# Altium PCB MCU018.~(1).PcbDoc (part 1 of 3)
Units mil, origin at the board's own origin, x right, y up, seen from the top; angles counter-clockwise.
Board outline 4035 x 4400 mil, 2 copper layers (Top Layer, Bottom Layer), stack 62 mil thick; 270 components, 230 nets, 958 pads, 568 vias.
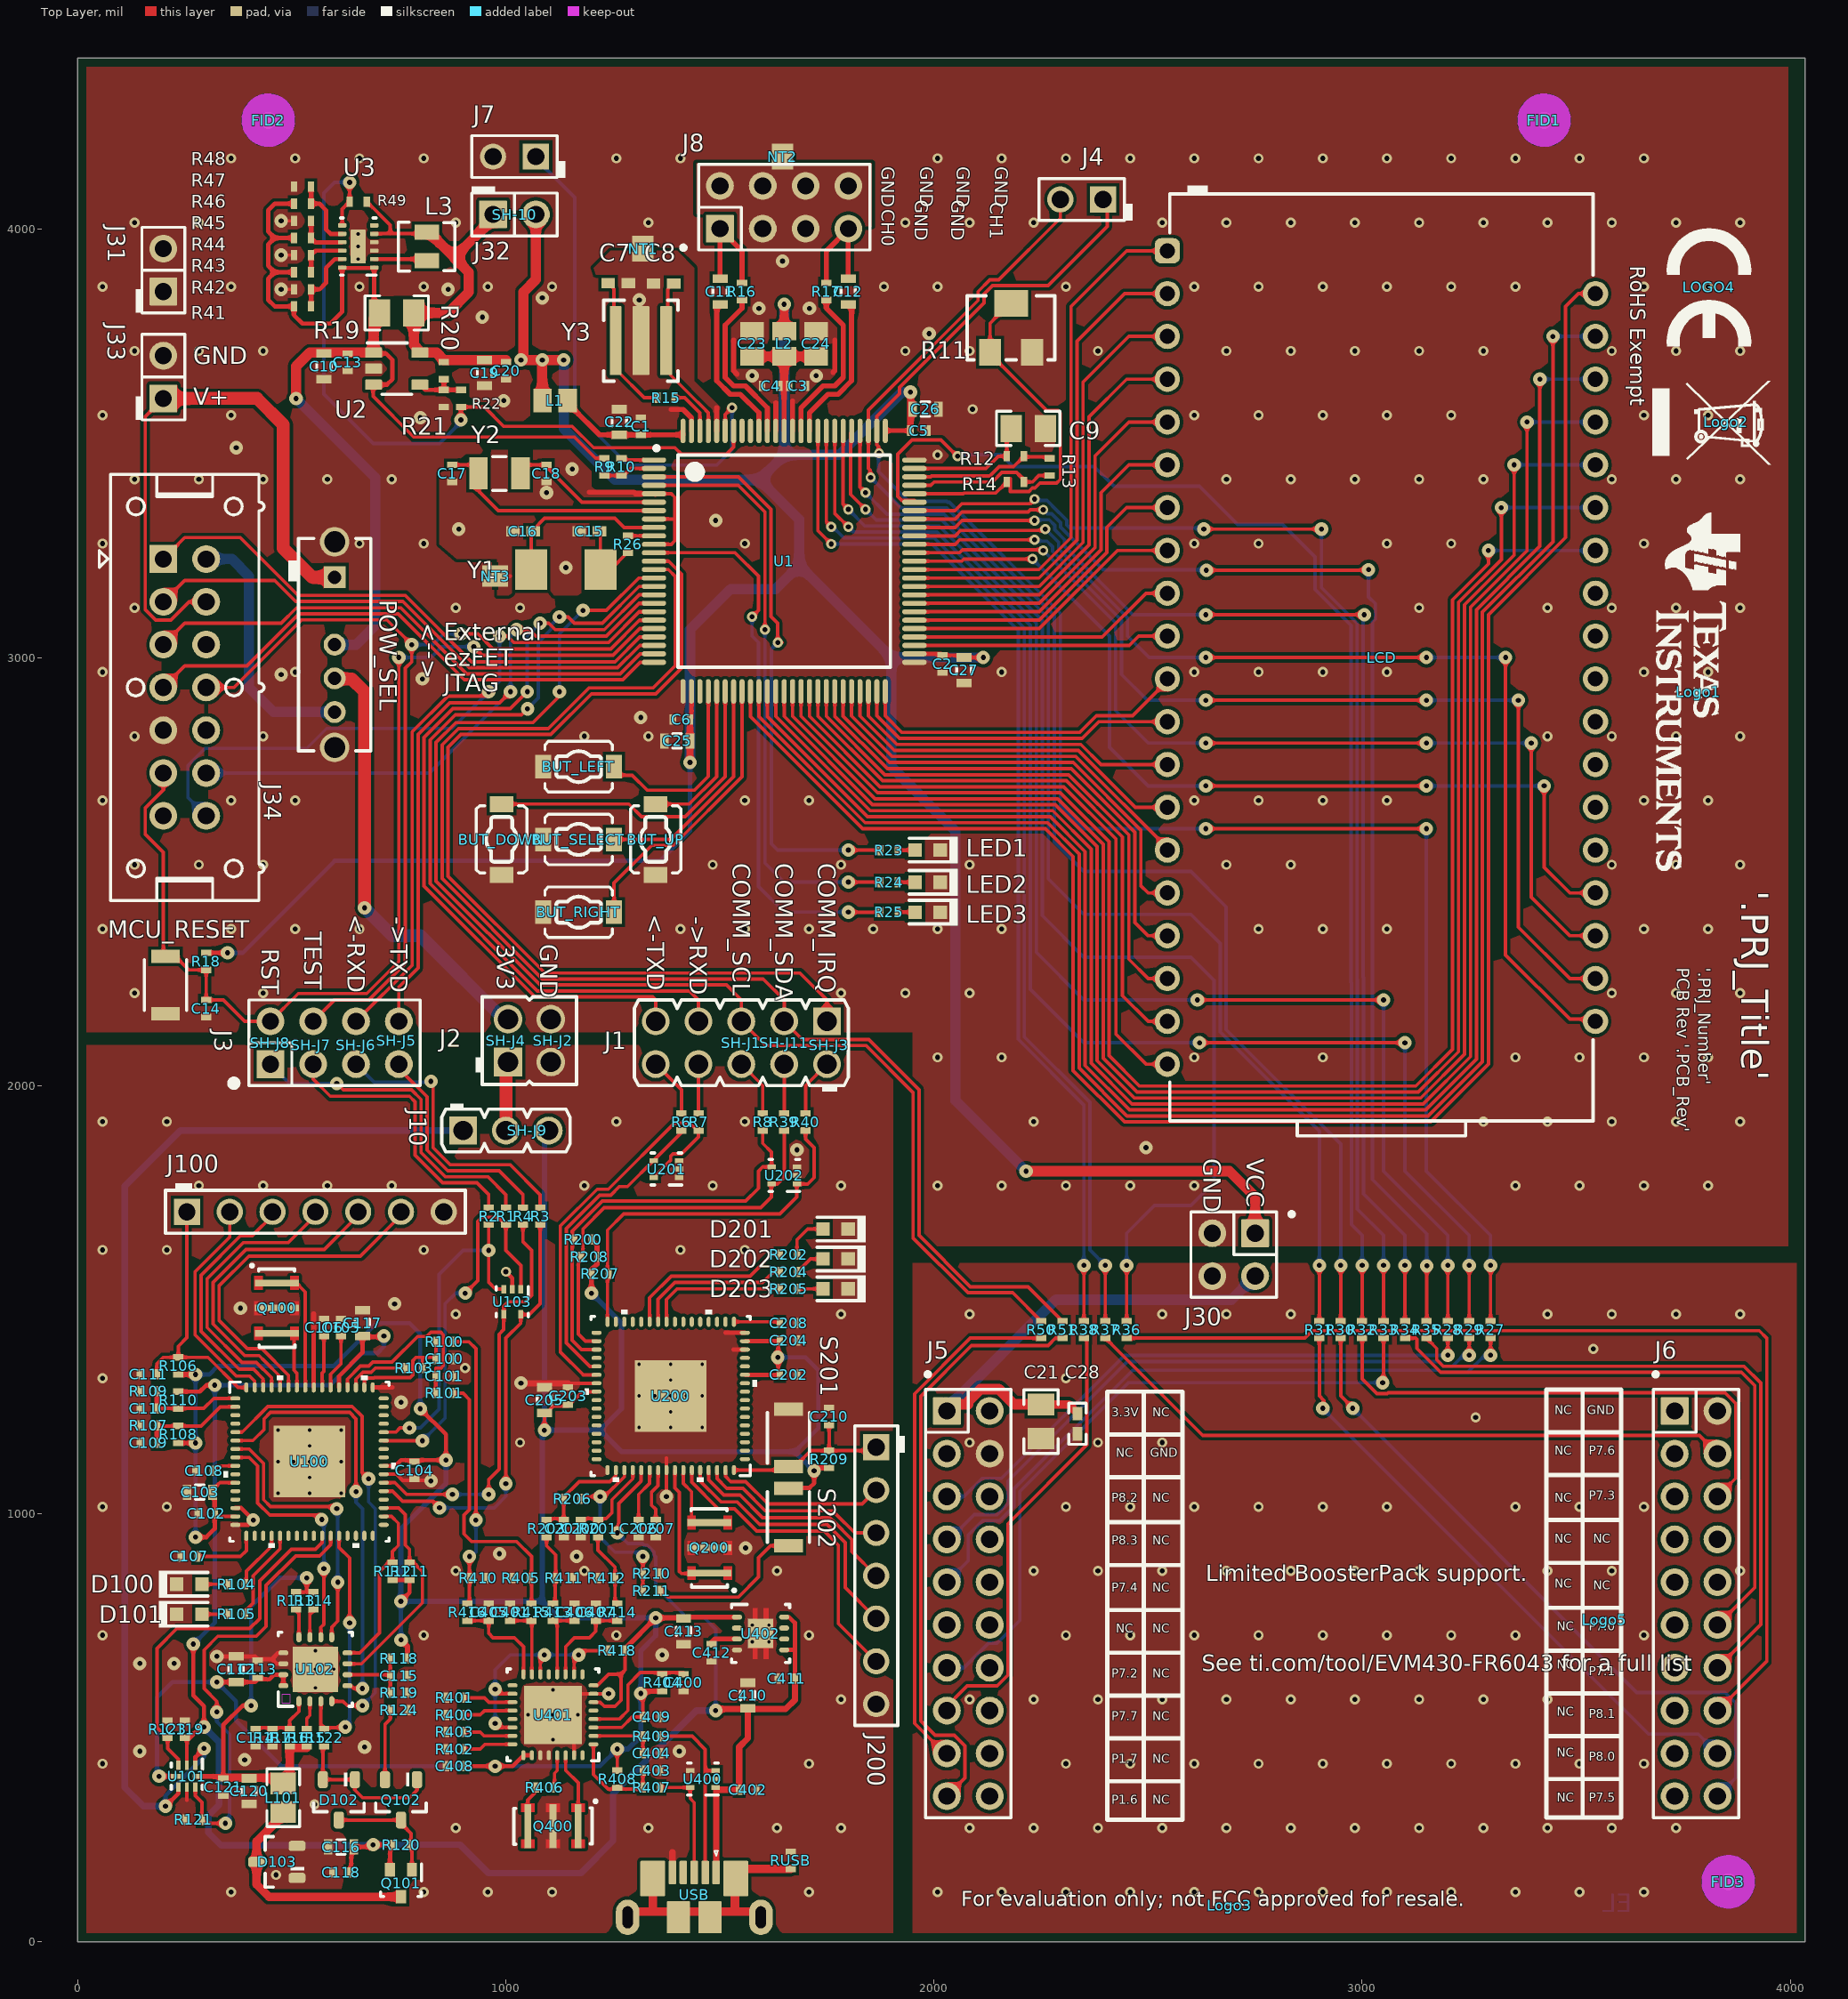
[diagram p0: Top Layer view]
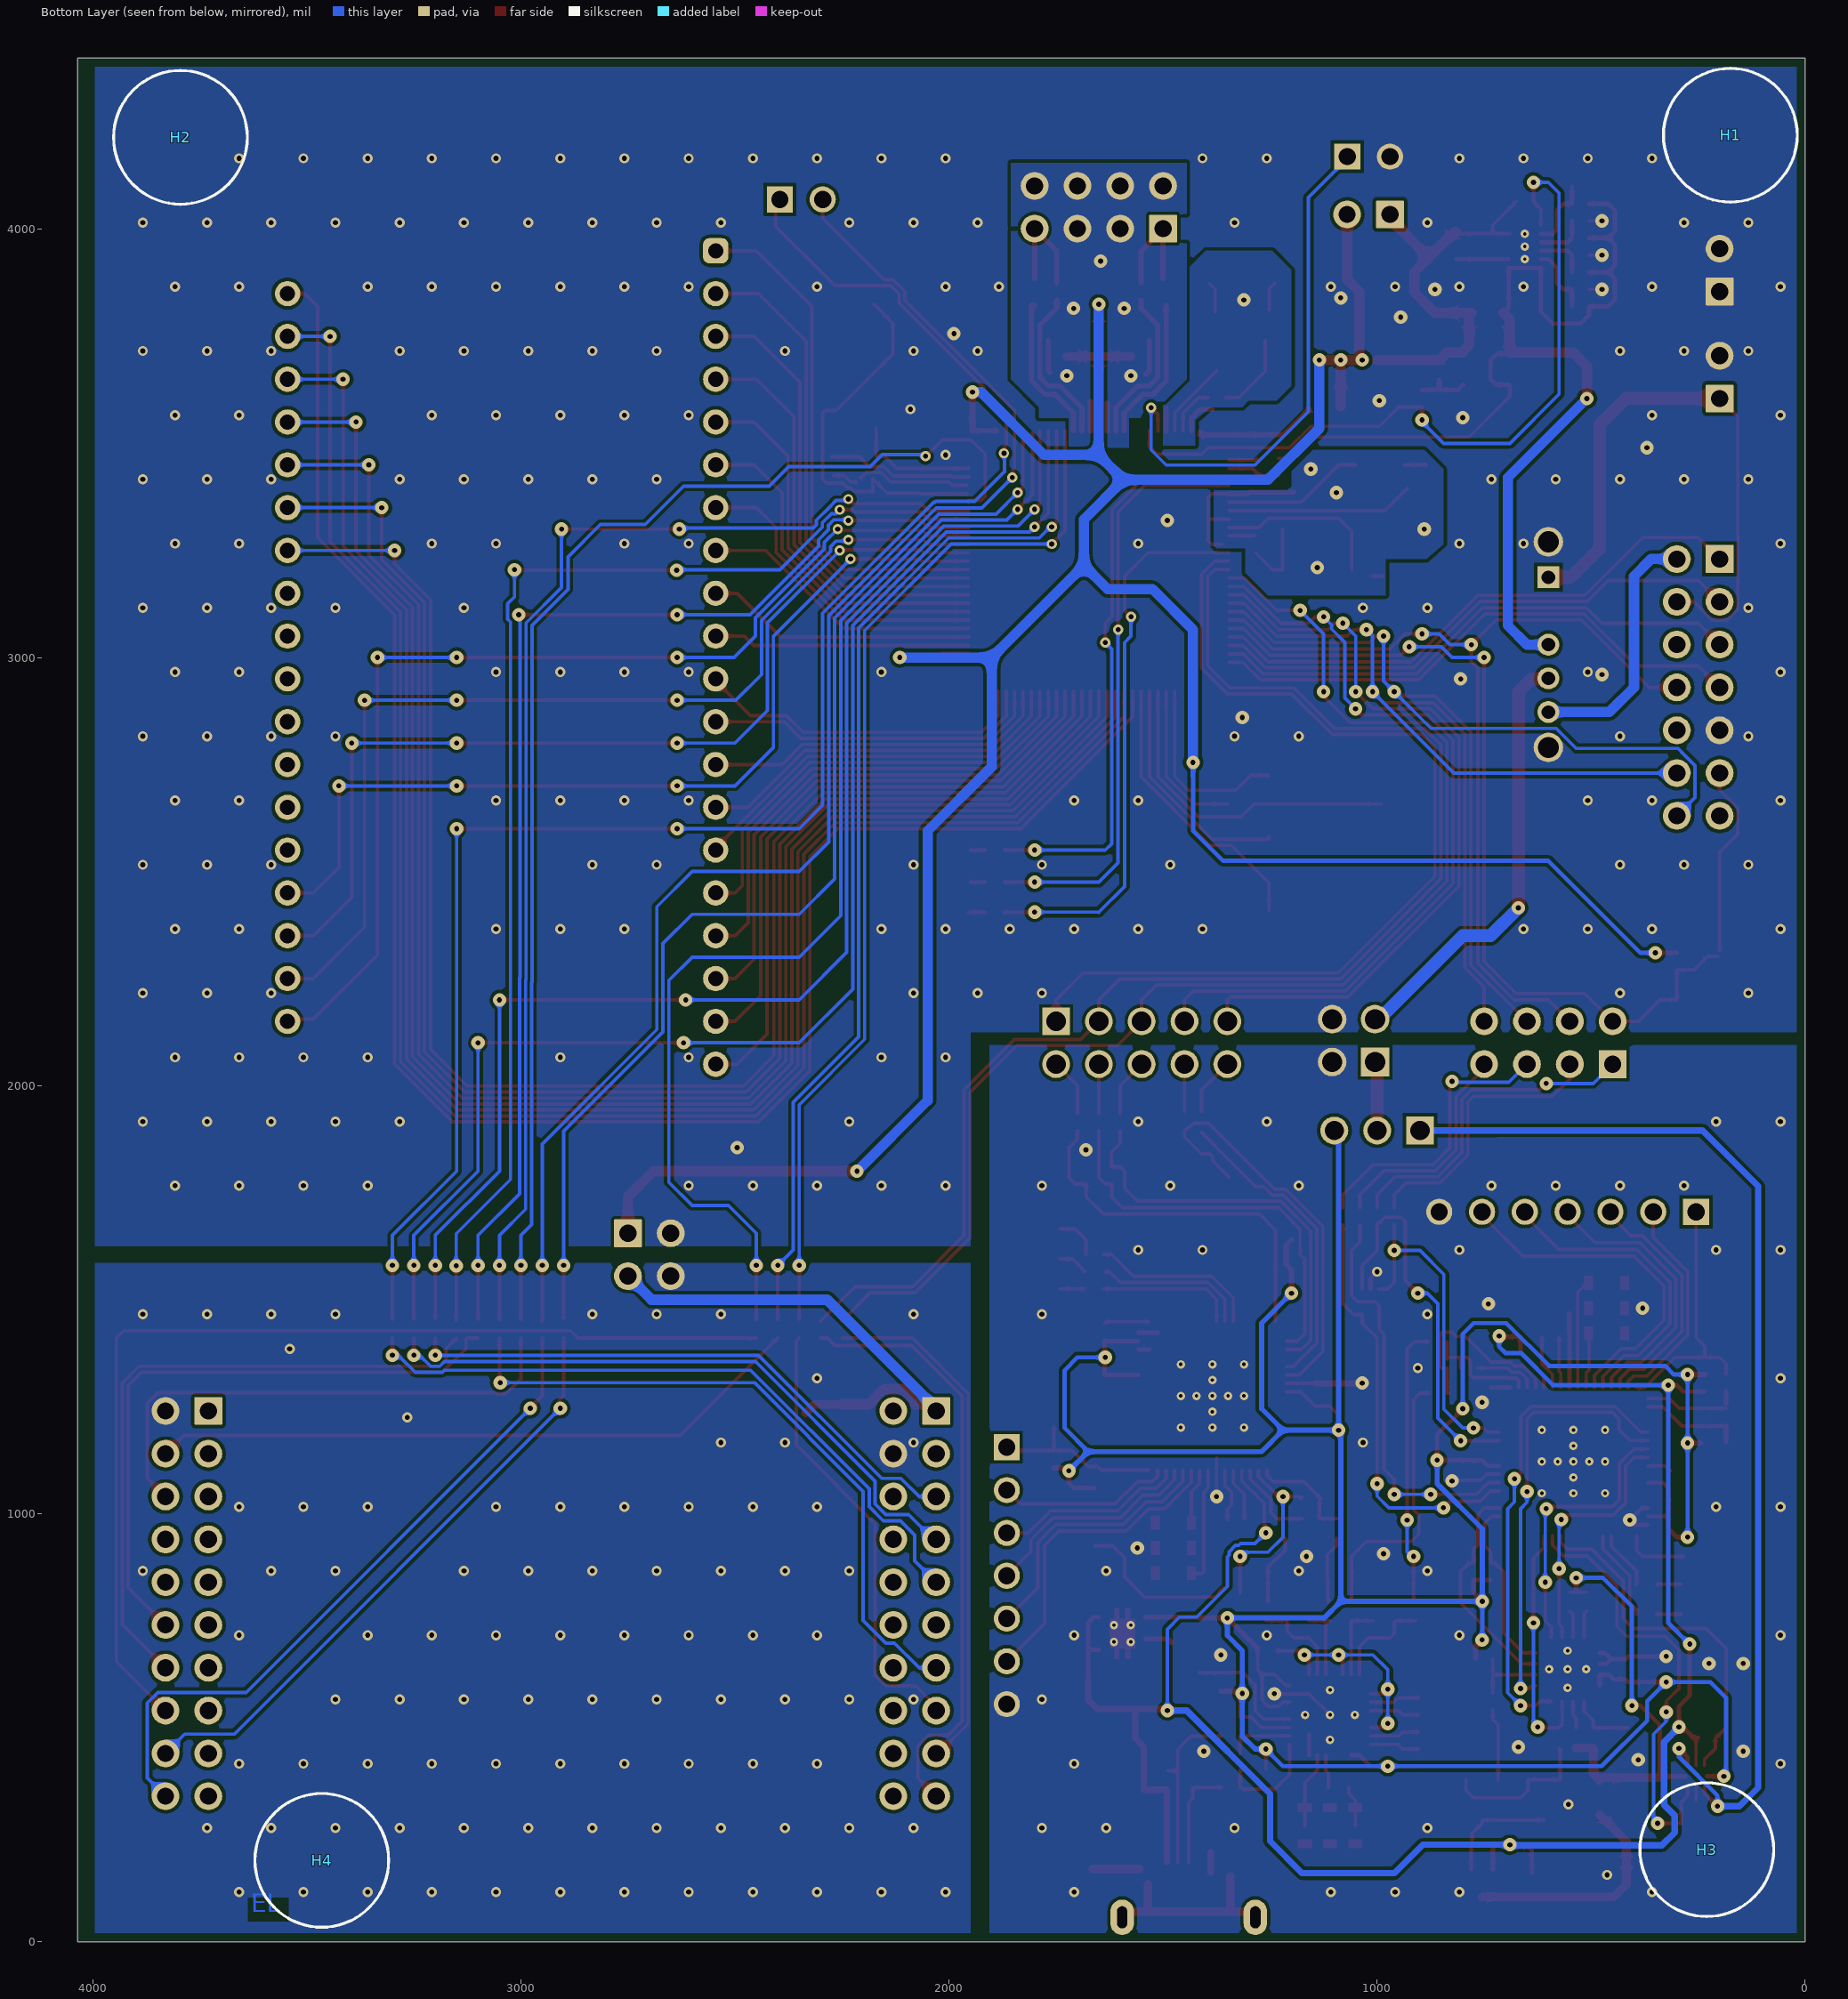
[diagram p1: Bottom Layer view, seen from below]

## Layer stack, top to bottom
Top Solder: solder mask 0.4, Solder Resist, Dk 3.5
Top Layer: signal copper 1.4
Dielectric1: core 59.2, FR-4, Dk 4.8
Bottom Layer: signal copper 1.4
Bottom Solder: solder mask 0.4, Solder Resist, Dk 3.5

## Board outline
0,0 0,4400 4035,4400 4035,0

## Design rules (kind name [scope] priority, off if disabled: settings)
AcuteAngle [All] p1: minimum=4.50000000000000E+0001 checktracksonly=FALSE
AssemblyTestPointUsage [All] p1: valid=2
BoardOutlineClearance BoardOutlineClearance_2 [InComponent('USB')] p1: gap=0 ignorepadtopadclearanceinfootprint=FALSE
BoardOutlineClearance BoardOutlineClearance_1 [InNet('USB_SHIELD')] p2: gap=0 ignorepadtopadclearanceinfootprint=FALSE
BoardOutlineClearance BoardOutlineClearance_MountingHoles [OnCopper and InComponentClass('Mounting Holes')] p3: gap=39.37 ignorepadtopadclearanceinfootprint=FALSE
BoardOutlineClearance BoardOutlineClearance_Poly [OnCopper and InPoly] p4: gap=20 ignorepadtopadclearanceinfootprint=FALSE
BoardOutlineClearance [OnCopper and Not InComponentClass('Logo') and not InComponentClass('FiducialMark') and not InRegion(1000,500,4000,800)] p5: gap=20 ignorepadtopadclearanceinfootprint=FALSE
Clearance Clearance_FID [HasFootprint('Fiducial10-30')] p1: gap=0 ignorepadtopadclearanceinfootprint=FALSE
Clearance "Stitching TARGET_GND" [IsStitchingVia and InNet('TARGET_GND') vs (IsVia and (Not IsStitchingVia)) Or IsPad] p2: gap=2 ignorepadtopadclearanceinfootprint=FALSE except(0: Arc-Hole Track-Hole SMDPad-Hole THPad-Hole Via-Hole Fill-Hole Poly-Hole Region-Hole Text-Hole)
Clearance Clearance_Keepouts [((IsTrack Or IsArc) And Not InPoly) And IsFree and IsKeepOut vs ((IsTrack Or IsArc) And Not InPoly) And IsFree and IsKeepOut] p3: gap=0 ignorepadtopadclearanceinfootprint=FALSE
Clearance Clearance_Poly [InPolygon] p4: gap=7.8 ignorepadtopadclearanceinfootprint=FALSE except(0: Arc-Hole Track-Hole SMDPad-Hole THPad-Hole Via-Hole Fill-Hole Poly-Hole Region-Hole Text-Hole)
Clearance [All] p5: gap=6 ignorepadtopadclearanceinfootprint=FALSE except(0: Arc-Hole Track-Hole SMDPad-Hole THPad-Hole Via-Hole Fill-Hole Poly-Hole Region-Hole Text-Hole)
ComponentClearance ComponentClearance_shunt1 [HasFootprint('Wurth_60900213421')] p1: gap=0 collisioncheckmode=3 verticalgap=0 showdistances=FALSE
ComponentClearance [InComponent('NT2') vs InComponent('J8')] p2: gap=0 collisioncheckmode=3 verticalgap=0 showdistances=FALSE
ComponentClearance ComponentClearance_MountingHoles_FiducialMarks [InComponentClass('Mounting Holes') vs InComponentClass('FiducialMark')] p3: gap=50 collisioncheckmode=3 verticalgap=10 showdistances=FALSE
ComponentClearance ComponentClearance_Shunt [InComponentClass('Header') vs InComponentClass('Shunt')] p4: gap=0 collisioncheckmode=3 verticalgap=0 showdistances=FALSE
ComponentClearance ComponentClearance_Logo [InComponentClass('Logo')] p5: gap=50 collisioncheckmode=3 verticalgap=10 showdistances=FALSE
ComponentClearance ComponentClearance_ScrewToNut [(HasFootprint('BuildingFastener_MPMS_003_0005_PH')) vs (HasFootprint('Keystone_24434'))] p6: gap=0 collisioncheckmode=3 verticalgap=0 showdistances=FALSE
ComponentClearance ComponentClearance_MountingHoles [InComponentClass('Mounting Holes')] p7: gap=250 collisioncheckmode=3 verticalgap=100000 showdistances=FALSE
ComponentClearance ComponentClearance_SmallPassives [HasFootprint('0201*') or HasFootprint('0402*') or HasFootprint('0508') or HasFootprint('0603*') or HasFootprint('0612') or HasFootprint('0805*') or HasFootprint('0815*') or HasFootprint('0830*') or HasFootprint('1206*') or HasFootprint('1210*') or HasFootprint('1808*') or HasFootprint('1812*') or HasFootprint('1825*') or HasFootprint('2010*') or HasFootprint('2220*') or HasFootprint('2225*') or HasFootprint('2512*') or HasFootprint('2728*') or HasFootprint('3518*') vs HasFootprint('0201*') or HasFootprint('0402*') or HasFootprint('0508') or HasFootprint('0603*') or HasFootprint('0612') or HasFootprint('0805*') or HasFootprint('0815*') or HasFootprint('0830*') or HasFootprint('1206*') or HasFootprint('1210*') or HasFootprint('1808*') or HasFootprint('1812*') or HasFootprint('1825*') or HasFootprint('2010*') or HasFootprint('2220*') or HasFootprint('2225*') or HasFootprint('2512*') or HasFootprint('2728*') or HasFootprint('3518*')] p8: gap=14.96 collisioncheckmode=3 verticalgap=10 showdistances=FALSE
ComponentClearance ComponentClearance_THtoSMT [IsThruComponent vs IsSMTComponent] p9: gap=15 collisioncheckmode=3 verticalgap=30 showdistances=FALSE
ComponentClearance ComponentClearance_THtoTH [IsThruComponent vs IsThruComponent] p10: gap=30 collisioncheckmode=3 verticalgap=30 showdistances=FALSE
DiffPairsRouting [All] p1: maxlimit=100 minlimit=10 mostfreqgap=10 toplayer_minwidth=15 toplayer_maxwidth=15 toplayer_prefwidth=15 bottomlayer_minwidth=15 bottomlayer_maxwidth=15 bottomlayer_prefwidth=15 maxuncoupledlength=1000
FabricationTestPointUsage TestPointUsage [All] p1: valid=2 allowmultiple=FALSE
FabricationTestpoint Testpoint [All] p1: side=3 testpointundercomponent=TRUE minsize=40 maxsize=100 preferedsize=60 minholesize=0 maxholesize=40 preferedholesize=32 testpointgrid=1 allowsidetop=TRUE allowsidebottom=TRUE usegrid=TRUE gridtolerance=0.01
FanoutControl Fanout_LCC [IsLCC] p1: bgadir=Out bgaviamode=Centered fanoutstyle=Auto fanoutdirection=Alternating viagrid=1 // Fanout_LCC (Default Rule)
FanoutControl Fanout_BGA [IsBGA] p2: bgadir=Out bgaviamode=Centered fanoutstyle=Auto fanoutdirection=Alternating viagrid=1 // Fanout_BGA (Default Rule)
FanoutControl Fanout_Default [All] p4: bgadir=Out bgaviamode=Centered fanoutstyle=Auto fanoutdirection=Alternating viagrid=1 // Fanout_Default (Default Rule)
FanoutControl Fanout_Small [(CompPinCount < 5)] p5: bgadir=Out bgaviamode=Centered fanoutstyle=Auto fanoutdirection=OutThenIn viagrid=1 // Fanout_Small (Default Rule)
HoleSize [All] p1: absolutevalues=TRUE maxlimit=251 minlimit=7.87 maxpercent=80.000 minpercent=20.000
MinimumAnnularRing MinimumAnnularRing_ThermalPadVias [IsVia and InAnyComponent] p1: minimumring=5.91
MinimumAnnularRing [All] p2: minimumring=5.91
MinimumSolderMaskSliver MinimumSolderMaskSliver_Logo [InComponentClass('Logo') vs InComponentClass('Logo')] p1: minsoldermaskwidth=0.7
MinimumSolderMaskSliver [All] p2: minsoldermaskwidth=3.94
PlaneClearance [All] p1: clearance=10
PlaneConnect [All] p1: planeconnectstyle=Direct reliefexpansion=10 reliefentries=4 reliefconductorwidth=10 reliefairgap=10
PolygonConnect [All] p1: connectstyle=Direct reliefconductorwidth=10 reliefentries=4 polygonreliefangle="90 Angle" airgapwidth=10
RoutingVias ThermalPadVias [IsVia and InAnyComponent] p1: holewidth=11.81 width=19.68 viastyle="Through Hole" minholewidth=7.87 minwidth=19.68 maxholewidth=19.68 maxwidth=31.5
RoutingVias [All] p2: holewidth=11.81 width=31.5 viastyle="Through Hole" minholewidth=11.81 minwidth=23 maxholewidth=19.68 maxwidth=39.37
SilkToBoardRegionClearance [Not ((IsComment or IsDesignator) And (Hide <> 'False')) and not InRegion(1000,500,4000,800)] p1:
SilkToSilkClearance SilkToSilkClearance_Pb-FreeLogo [(HasFootprint('Pb-Free_Overlay_Medium') OR HasFootprint('Pb-Free_Overlay_Small')) vs (HasFootprint('Pb-Free_Overlay_Medium') OR HasFootprint('Pb-Free_Overlay_Small'))] p1: silktosilkclearance=0
SilkToSilkClearance [All] p2: silktosilkclearance=2
SilkToSolderMaskClearance SilkToComponentPadClearance [IsPad and InAnycomponent] p1: minsilkscreentomaskgap=5 clearancetoexposedcopper=TRUE
SilkToSolderMaskClearance "Silk to Solder Mask Opening" [All] p2: minsilkscreentomaskgap=4 clearancetoexposedcopper=FALSE
SolderMaskExpansion [All] p1: expansion=1.97
Width [All] p1: maxlimit=100 minlimit=7.8 preferedwidth=8 checkconnectedcopper=TRUE
14 further rules are at their usual default settings.

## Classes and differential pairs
component class Main: BUT_DOWN BUT_LEFT BUT_RIGHT BUT_SELECT BUT_UP C1 C2 C3 C4 C5 C6 C7 C8 C9 C10 C11 C12 C13 C14 C15 C16 C17 C18 C19 C20 C21 C22 C23 C24 C25 C26 C27 C28 J4 J5 J6 J7 J8 J30 J31 J32 J33 J34 J? L1 L2 L3 LCD LED1 LED2 LED3 MCU_RESET NT1 NT2 NT3 POW_SEL R9 R10 R11 R12 R13 R14 R15 R16 R17 R18 R19 R20 R21 R22 R23 R24 R25 R26 R27 R28 R29 R30 R31 R32 R33 R34 R35 R36 R37 R38 R41 R42 R43 R44 R45 R46 R47 R48 R49 R50 R51 R? U1 U2 U3 Y1 Y2 Y3
component class "MCU018_Banshee Flow Meter EVM(original)": J1 J2 J3 J10 R1 R2 R3 R4 R6 R7 R8 R39 R40 RUSB USB
component class AssemblyNote: ZZ2 ZZ3 ZZ4
component class U_EVM430-FR6043_HW: FID1 FID2 FID3 H1 H2 H3 H4 Logo1 Logo2 Logo3 LOGO4 Logo5 SH-10 SH-J1 SH-J2 SH-J3 SH-J4 SH-J5 SH-J6 SH-J7 SH-J8 SH-J9 SH-J11 ZZ2 ZZ3 ZZ4
component class Logo: Logo1
component class Header: J1 J2 J3 J4 J5 J6 J7 J8 J10 J30 J31 J32 J33 J100 J200 J?
component class "USB Hub": C400 C401 C402 C403 C404 C405 C406 C407 C408 C409 C410 C411 C412 C413 Q400 R400 R401 R402 R403 R404 R405 R406 R407 R408 R409 R410 R411 R412 R413 R414 R415 R416 R418 U400 U401 U402
component class "HID Bridge": C200 C201 C202 C203 C204 C205 C206 C207 C208 C210 D201 D202 D203 J200 Q200 R200 R201 R202 R203 R204 R205 R206 R207 R208 R209 R210 R211 S201 S202 U200 U201 U202
component class eZFET: C100 C101 C102 C103 C104 C105 C106 C107 C108 C109 C110 C111 C112 C113 C114 C115 C116 C117 C118 C119 C120 C121 D100 D101 D102 D103 J100 L101 Q100 Q101 Q102 R100 R101 R103 R104 R105 R106 R107 R108 R109 R110 R111 R112 R113 R114 R115 R116 R117 R118 R119 R120 R121 R122 R123 R124 U100 U101 U102 U103
component class FiducialMark: FID1 FID2 FID3
component class Shunt: SH-10 SH-J1 SH-J2 SH-J3 SH-J4 SH-J5 SH-J6 SH-J7 SH-J8 SH-J9 SH-J11
net class Power_Nets: EZFET_TARGET_VCC EZFET_VCC EZFET_VCCTARGET USB_VBUS

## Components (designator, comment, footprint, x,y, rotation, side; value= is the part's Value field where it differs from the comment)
BUT_DOWN "TL1015AF160QG" SW_TL1015AF160QG 990,2575 r90 top
BUT_LEFT "TL1015AF160QG" SW_TL1015AF160QG 1170,2745 r0 top
BUT_RIGHT "TL1015AF160QG" SW_TL1015AF160QG 1170,2405 r0 top
BUT_SELECT "TL1015AF160QG" SW_TL1015AF160QG 1170,2575 r0 top
BUT_UP "TL1015AF160QG" SW_TL1015AF160QG 1350,2575 r90 top
C1 "GRM155R71C104KA88D" 0402S 1315,3540 r90 top value=0.1uF
C2 "GRM155R71C104KA88D" 0402S 2020,2985 r90 top value=0.1uF
C3 "GRM1555C1H102JA01D" 0402S 1681.5,3634.45 r180 top value=1000pF
C4 "GRM1555C1H102JA01D" 0402S 1618.5,3634.45 r180 top value=1000pF
C5 "GRM155R71C104KA88D" 0402S 1965,3530 r0 top value=0.1uF
C6 "GRM155R71C104KA88D" 0402S 1410,2855 r180 top value=0.1uF
C7 "GRM1555C1H120JA01D" 0402 1262.36,3874.61 r0 top value=12pF
C8 "GRM1555C1H120JA01D" 0402 1368.35,3873.54 r180 top value=12pF
C9 "GRM21BR71C475KA73L" 0805_HV 2220,3535 r0 top value=4.7uF
C10 "GRM188R61A106ME69D" 0603S 575,3680 r270 top value=10uF
C11 "GRM1885C1H102FA01J" 0603S 1500.39,3854.92 r90 top value=1000pF
C12 "GRM1885C1H102FA01J" 0603S 1799.61,3854.92 r90 top value=1000pF
C13 "GRM155R71C104KA88D" 0402S 630,3690 r270 top value=0.1uF
C14 "GRM1555C1H102JA01D" 0402S 300,2180 r270 top value=1000pF
C15 "GRM1555C1H120JA01D" 0402 1195,3295 r180 top value=12pF
C16 "GRM1555C1H120JA01D" 0402 1040,3295 r180 top value=12pF
C17 "GRM1555C1H120JA01D" 0402S 875,3430 r90 top value=12pF
C18 "GRM1555C1H120JA01D" 0402S 1095,3430 r270 top value=12pF
C19 "GRM188R61A106ME69D" 0603S 950,3665 r270 top value=10uF
C20 "GRM155R71C104KA88D" 0402S 1000,3670 r270 top value=0.1uF
C21 "GRM21BR60J476ME15L" 0805_HV 2250,1215 r270 top value=47uF
C22 "GRM188R71A105KA61D" 0603S 1265,3550 r90 top value=1uF
C23 "GRM21BR60J476ME15L" 0805L 1575.2,3732.87 r90 top value=47uF
C24 "GRM21BR60J476ME15L" 0805L 1724.8,3732.87 r270 top value=47uF
C25 "GRM188R71A105KA61D" 0603S 1400,2805 r180 top value=1uF
C26 "GRM188R71A105KA61D" 0603S 1980,3580 r0 top value=1uF
C27 "GRM188R71A105KA61D" 0603S 2070,2970 r90 top value=1uF
C28 "GRM155R71C104KA88D" 0402 2335,1210 r270 top value=0.1uF
C100 "GRM1555C1H220JA01D" 0402S 856.39,1361.5 r0 top value=22pF
C101 "GRM1555C1H220JA01D" 0402S 856.39,1321.5 r0 top value=22pF
C102 "GRM155R71C104KA88D" 0402S 300,1000 r180 top value=0.1uF
C103 "GRM188R61A475MAAJ" 0603S 285,1050 r180 top value=4.7uF
C104 "GRM155R71C104KA88D" 0402S 786.39,1101.5 r270 top value=0.1uF
C105 "GRM155R71C224KA12D" 0402S 615,1435 r90 top value=0.22uF
C106 "GRM155R71C224KA12D" 0402S 575,1435 r90 top value=0.22uF
C107 "GRM155R61C474KE01" 0402S 260,900.1 r180 top value=0.47uF
C108 "GRM155R71C104KA88D" 0402S 295,1100 r180 top value=0.1uF
C109 "GRM1555C1H330JA01D" 0402S 165,1166 r180 top value=33pF
C110 "GRM1555C1H330JA01D" 0402S 165,1246 r180 top value=33pF
C111 "GRM1555C1H102JA01D" 0402S 165,1326 r180 top value=1000pF
C112 "GRM188R61A475MAAJ" 0603S 370,636.5 r90 top value=4.7uF
C113 "GRM155R71C104KA88D" 0402S 420,636.5 r90 top value=0.1uF
C114 "GRM1555C1H330JA01D" 0402S 415,476.5 r270 top value=33pF
C115 "GRM1555C1H330JA01D" 0402S 750,621.5 r0 top value=33pF
C116 "GRM188R61A475MAAJ" 0603S 615,221.5 r180 top value=4.7uF
C117 "GRM188R61A475MAAJ" 0603S 665,1445 r90 top value=4.7uF
C118 "GRM155R71C104KA88D" 0402S 615,161.5 r180 top value=0.1uF
C119 "GRM155R71C104KA88D" 0402S 250,496.5 r90 top value=0.1uF
C120 "GRM188R61A475MAAJ" 0603S 400,351.5 r270 top value=4.7uF
C121 "GRM155R71C104KA88D" 0402S 340,361.5 r270 top value=0.1uF
C200 "GRM1555C1H220JA01D" 0402S 1175,965 r270 top value=22pF
C201 "GRM1555C1H220JA01D" 0402S 1135,965 r270 top value=22pF
C202 "GRM155R71C104KA88D" 0402S 1660,1325 r0 top value=0.1uF
C203 "GRM155R71C104KA88D" 0402S 1145,1275 r90 top value=0.1uF
C204 "GRM155R71C104KA88D" 0402S 1660,1405 r0 top value=0.1uF
C205 "GRM188R61A475MAAJ" 0603S 1090,1265 r90 top value=4.7uF
C206 "GRM155R71C224KA12D" 0402S 1310,965 r270 top value=0.22uF
C207 "GRM155R71C224KA12D" 0402S 1350,965 r270 top value=0.22uF
C208 "GRM155R61C474KE01" 0402S 1660,1445 r0 top value=0.47uF
C210 "GRM1555C1H102JA01D" 0402S 1755,1227.05 r90 top value=1000pF
C400 "GRM155R71C104KA88D" 0402S 1415,605 r270 top value=0.1uF
C401 "GRM1555C1H100JA01D" 0402S 1010,770 r90 top value=10pF
C402 "GRM155R71C104KA88D" 0402S 1565,355 r0 top value=0.1uF
C403 "GRM1555C1H220JA01D" 0402S 1340,400 r0 top value=22pF
C404 "GRM1555C1H220JA01D" 0402S 1340,440 r0 top value=22pF
C405 "GRM1555C1H100JA01D" 0402S 960,770 r90 top value=10pF
C406 "GRM1555C1H100JA01D" 0402S 1160,770 r90 top value=10pF
C407 "GRM1555C1H100JA01D" 0402S 1210,770 r90 top value=10pF
C408 "GRM155R71C104KA88D" 0402S 880,410 r180 top value=0.1uF
C409 "GRM155R71C104KA88D" 0402S 1340,525 r0 top value=0.1uF
C410 "GRM188R61A106ME69D" 0603S 1565,575 r90 top value=10uF
C411 "GRM155R71C104KA88D" 0402S 1655,615 r180 top value=0.1uF
C412 "GRM155R71C103KA01D" 0402S 1480,675 r270 top value=0.01uF
C413 "GRM188R61A106ME69D" 0603S 1415,725 r270 top value=10uF
D100 "LTST-C190CKT" LED_LTST-C190_Red 260.47,835.1 r180 top value=Red
D101 "LTST-C191TGKT" LTST-C191_Green 260.47,765.1 r180 top value=Green
D102 "BAS40-05-7-F" SOT-23 610,331.5 r270 top value=40V
D103 "BAS40-05-7-F" SOT-23 465,186.5 r180 top value=40V
D201 "LTST-C191TGKT" LTST-C191_Green 1770,1665 r0 top value=Green
D202 "LTST-C191TGKT" LTST-C191_Green 1770,1595 r0 top value=Green
D203 "LTST-C190CKT" LED_LTST-C190_Red 1770,1525 r0 top value=Red
FID1 "Fiducial" Fiducial10-30 3425,4255 r0 top
FID2 "Fiducial" Fiducial10-30 445,4255 r0 top
FID3 "Fiducial" Fiducial10-30 3855,140 r0 top
H1 "SJ61A1" Bumpon_SJ61A1 175,4220 r90 bottom
H2 "SJ61A1" Bumpon_SJ61A1 3795,4215 r90 bottom
H3 "SJ61A1" Bumpon_SJ61A1 230,215 r90 bottom
H4 "SJ61A1" Bumpon_SJ61A1 3465,190 r90 bottom
J1 "61301021121" WURTH_61301021121 1550,2100 r180 top
J2 "PBC02DAAN" Sullins_PxC02DAAN 1055,2105 r90 top
J3 "PEC04DAAN" CONN_PEC04DAAN 600,2100 r0 top
J4 "HMTSW-102-07-G-S-240" SAMTEC_HMTSW-102-07-G-S-240 2345,4070 r180 top
J5 "TSW-110-07-G-D" TSW-110-07-G-D 2080,790 r270 top
J6 "TSW-110-07-G-D" TSW-110-07-G-D 3780,790 r270 top
J7 "HMTSW-102-07-G-S-240" SAMTEC_HMTSW-102-07-G-S-240 1020,4170 r180 top
J8 "TSW-104-07-G-D" TSW-104-07-G-D 1650,4051.77 r0 top
J10 "61300311121" WURTH_61300311121 1000,1895 r0 top
J30 "TSW-102-07-G-D" TSW-102-07-G-D 2700,1605 r180 top
J31 "TSW-102-07-G-S" TSW-102-07-G-S 200,3905 r90 top
J32 "TSW-102-07-G-S" TSW-102-07-G-S 1020,4035 r0 top
J33 "TSW-102-07-G-S" TSW-102-07-G-S 200,3655 r90 top
J34 "SBH11-PBPC-D07-ST-BK" CONN_SBH11-PBPC-D07-ST-BK 250,2930 r270 top
J100 "PBC07SAAN" Sullins_xxC07SAAN 555,1705 r0 top
J200 "PBC07SAAN" Sullins_xxC07SAAN 1865,855 r270 top
L1 "MPZ2012S601A" 0805L 1115,3600 r180 top value="600 ohm"
L2 "MPZ2012S601A" 0805L 1650.32,3732.87 r90 top value="600 ohm"
L3 "VLF302515MT-2R2M" VLF302515MT 815,3960 r90 top value=2.2uH
L101 "CIG21L2R2MNE" 0805 480,336.5 r90 top value=2.2uH
LCD "FH-1138P" ADKOM_FH-1138P 3045,3000 r0 top
LED1 "LTST-C191TGKT" LTST-C191_Green 1985,2550 r0 top value=Green
LED2 "LTST-C191TGKT" LTST-C191_Green 1985,2475 r0 top value=Green
LED3 "LTST-C190CKT" LED_LTST-C190_Red 1985,2405 r0 top value=Red
Logo1 "Texas Instruments" TI_Stacked_Overlay_Small 3785,2920 r270 top
Logo2 "WEEE logo" WEEE_Minimum 3850,3550 r270 top
Logo3 "FCC disclaimer" FCC_disclaimer 2690,85 r0 top
LOGO4 "CE Mark" CE_Mark_5mm 3810,3865 r270 top
Logo5 "EU RoHS Exempt Logo" EURoHS_Exempt_60mil 3566,752 r0 top
MCU_RESET "B3U-1000P" SW_B3U-1000P 205,2235 r90 top
NT1 "Net-Tie" Net-Tie_50milWide_30milLong 1320,3955 r90 top net-tie
NT2 "Net-Tie" Net-Tie_50milWide_30milLong 1646.06,4169.88 r90 top net-tie
NT3 "Net-Tie" Net-Tie_50milWide_30milLong 975,3190 r180 top net-tie
POW_SEL "SS-13D16-VG 4 PA" SW_SS-13D16-VG 600,3030 r270 top
Q100 "CSTCR4M00G15L99-R0" Murata_CSTCR 465,1480 r270 top
Q101 "DMG1013UW" SOT-323 755,136.5 r270 top value=-50V
Q102 "BC850CLT1G" SOT-23 755,331.5 r270 top value=0.7V
Q200 "CSTCR4M00G15L99-R0" Murata_CSTCR 1475,920 r90 top
Q400 "CSTCR6M00G53Z-R0" Murata_CSTCR 1110,270 r180 top
R1 "CRCW0402100RJNED" 0402S 1000,1695 r90 top value=100
R2 "CRCW0402100RJNED" 0402S 960,1695 r90 top value=100
R3 "CRCW0402100RJNED" 0402S 1080,1695 r90 top value=100
R4 "CRCW0402100RJNED" 0402S 1040,1695 r90 top value=100
R6 "CRCW0402100RJNED" 0402S 1410,1915 r90 top value=100
R7 "CRCW0402100RJNED" 0402S 1450,1915 r90 top value=100
R8 "CRCW0402100RJNED" 0402S 1600,1915 r90 top value=100
R9 "CRCW0402100KJNED" 0402S 1230,3445 r90 top value=100k
R10 "CRCW0402100KJNED" 0402S 1270,3445 r270 top value=100k
R11 "3224W-1-204E" TRIM_3224W 2180,3770 r90 top value=200k
R12 "CRCW0402330KJNED" 0402S 2190,3470 r180 top value=330k
R13 "CRCW0402330KJNED" 0402S 2270,3445 r90 top value=330k
R14 "CRCW0402330KJNED" 0402S 2190,3410 r180 top value=330k
R15 "CRCW040222R0JNED" 0402S 1374.41,3606.89 r0 top value=22
R16 "CRCW0402200RFKED" 0402S 1551.57,3854.92 r270 top value=200
R17 "CRCW0402200RFKED" 0402S 1748.43,3854.92 r270 top value=200
R18 "CRCW040247K0JNED" 0402S 300,2290 r90 top value=47k
R19 "CRCW08050000Z0EA" 0805_HV 745,3805 r180 top value=0
R20 "Used in BOM report" 0402S 855,3670 r90 top
R21 "Used in BOM report" 0402S 855,3605 r90 top
R22 "Used in BOM report" 0402S 895,3605 r90 top
R23 "CRCW0402390RJNED" 0402S 1895,2550 r0 top value=390
R24 "CRCW0402390RJNED" 0402S 1895,2475 r0 top value=390
R25 "CRCW0402470RJNED" 0402S 1895,2405 r0 top value=470
R26 "CRCW040222R0JNED" 0402S 1284.92,3264.37 r90 top value=22
R27 "CRCW04020000Z0ED" 0402S 3300,1430 r90 top value=0
R28 "CRCW04020000Z0ED" 0402S 3200,1430 r90 top value=0
R29 "CRCW04020000Z0ED" 0402S 3250,1430 r90 top value=0
R30 "CRCW04020000Z0ED" 0402S 2950,1430 r90 top value=0
R31 "CRCW04020000Z0ED" 0402S 2900,1430 r90 top value=0
R32 "CRCW04020000Z0ED" 0402S 3000,1430 r90 top value=0
R33 "CRCW04020000Z0ED" 0402S 3050,1430 r270 top value=0
R34 "CRCW04020000Z0ED" 0402S 3100,1430 r90 top value=0
R35 "CRCW04020000Z0ED" 0402S 3150,1430 r90 top value=0
R36 "CRCW04020000Z0ED" 0402S 2450,1430 r270 top value=0
R37 "CRCW04020000Z0ED" 0402S 2400,1430 r270 top value=0
R38 "CRCW04020000Z0ED" 0402S 2350,1430 r270 top value=0
R39 "CRCW0402100RJNED" 0402S 1650,1915 r90 top value=100
R40 "CRCW0402100RJNED" 0402S 1700,1915 r90 top value=100
R41 "Used in BOM report" 0402S 525,3820 r180 top
R42 "Used in BOM report" 0402S 525,3860 r180 top
R43 "Used in BOM report" 0402S 525,3900 r180 top
R44 "Used in BOM report" 0402S 525,3940 r180 top
R45 "Used in BOM report" 0402S 525,3980 r180 top
R46 "Used in BOM report" 0402S 525,4020 r180 top
R47 "Used in BOM report" 0402S 525,4060 r180 top
R48 "Used in BOM report" 0402S 525,4100 r180 top
R49 "Used in BOM report" 0402S 655,4065 r180 top
R50 "CRCW04020000Z0ED" 0402S 2250,1430 r270 top value=0
R51 "CRCW04020000Z0ED" 0402S 2300,1430 r270 top value=0
R100 "CRCW040222R0JNED" 0402S 856.39,1401.5 r180 top value=22
R101 "CRCW040222R0JNED" 0402S 856.39,1281.5 r180 top value=22
R103 "CRCW04021K50JNED" 0402S 785,1340 r0 top value=1.5k
R104 "CRCW0402470RJNED" 0402S 370.47,835.1 r0 top value=470
R105 "CRCW0402390RJNED" 0402S 370.47,765.1 r0 top value=390
R106 "CRCW040247K0JNED" 0402S 235,1345 r270 top value=47k
R107 "CRCW0402221KFKED" 0402S 165,1206 r0 top value=221k
R108 "CRCW0402221KFKED" 0402S 235,1185 r270 top value=221k
R109 "CRCW0402150KFKED" 0402S 165,1286 r0 top value=150k
R110 "CRCW0402240KFKED" 0402S 235,1265 r90 top value=240k
R111 "CRCW04024K70JNED" 0402S 775,865 r90 top value=4.7k
R112 "CRCW04024K70JNED" 0402S 735,865 r90 top value=4.7k
R113 "CRCW04022K20FKED" 0402S 510,796.5 r90 top value=2.20k
R114 "CRCW04026K81FKED" 0402S 550,796.5 r90 top value=6.81k
R115 "CRCW04023K32FKED" 0402S 535,476.5 r90 top value=3.32k
R116 "CRCW0402221KFKED" 0402S 495,476.5 r270 top value=221k
R117 "CRCW0402221KFKED" 0402S 455,476.5 r90 top value=221k
R118 "CRCW0402221KFKED" 0402S 750,661.5 r180 top value=221k
R119 "CRCW0402221KFKED" 0402S 750,581.5 r180 top value=221k
R120 "CRCW0402470RJNED" 0402S 755,226.5 r0 top value=470
R121 "CRCW040247K0JNED" 0402S 270,285 r0 top value=47k
R122 "CRCW0402820RJNED" 0402S 575,476.5 r90 top value=820
R123 "CRCW040247K0JNED" 0402S 210,496.5 r270 top value=47k
R124 "CRCW04020000Z0ED" 0402S 750,541.5 r0 top value=0
R200 "CRCW04022K20JNED" 0402S 1180,1640 r0 top value=2.2k
R201 "CRCW040222R0JNED" 0402S 1215,965 r90 top value=22
R202 "CRCW0402390RJNED" 0402S 1660,1605 r180 top value=390
R203 "CRCW040222R0JNED" 0402S 1095,965 r90 top value=22
R204 "CRCW0402390RJNED" 0402S 1660,1565 r180 top value=390
R205 "CRCW0402470RJNED" 0402S 1660,1525 r180 top value=470
R206 "CRCW04021K50JNED" 0402S 1155,1035 r0 top value=1.5k
R207 "CRCW040210K0JNED" 0402S 1220,1560 r180 top value=10k
R208 "CRCW04022K20JNED" 0402S 1195,1600 r0 top value=2.2k
R209 "CRCW040247K0JNED" 0402S 1755,1127.05 r270 top value=47k
R210 "CRCW04021M00JNED" 0402S 1340,860 r180 top value=1.0Meg
R211 "CRCW0402100RJNED" 0402S 1340,820 r0 top value=100
R400 "CRCW040215K0JNED" 0402S 880,530 r0 top value=15k
R401 "CRCW040215K0JNED" 0402S 880,570 r180 top value=15k
R402 "CRCW040215K0JNED" 0402S 880,450 r180 top value=15k
R403 "CRCW040215K0JNED" 0402S 880,490 r180 top value=15k
R404 "CRCW040247K0JNED" 0402S 1365,605 r270 top value=47k
R405 "CRCW040215K0JNED" 0402S 1035,850 r0 top value=15k
R406 "CRCW040227R0JNED" 0402S 1090,360 r0 top value=27
R407 "CRCW040222R0JNED" 0402S 1340,360 r180 top value=22
R408 "CRCW04021K50JNED" 0402S 1260,380 r90 top value=1.5k
R409 "CRCW040222R0JNED" 0402S 1340,480 r180 top value=22
R410 "CRCW040215K0JNED" 0402S 935,850 r180 top value=15k
R411 "CRCW040215K0JNED" 0402S 1135,850 r180 top value=15k
R412 "CRCW040215K0JNED" 0402S 1235,850 r0 top value=15k
R413 "CRCW040222R0JNED" 0402S 1110,770 r270 top value=22
R414 "CRCW040222R0JNED" 0402S 1260,770 r270 top value=22
R415 "CRCW040222R0JNED" 0402S 1060,770 r270 top value=22
R416 "CRCW040222R0JNED" 0402S 910,770 r270 top value=22
R418 "CRCW040210K0JNED" 0402S 1258.62,680 r0 top value=10k
RUSB "CRCW040233R0JNED" 0402S 1665,190 r270 top value=33
S201 "B3U-1000P" SW_B3U-1000P 1660,1177.05 r270 top
S202 "B3U-1000P" SW_B3U-1000P 1660,992.05 r90 top
SH-10 "60900213421" Wurth_60900213421 1020,4035 r180 top
SH-J1 "60900213421" Wurth_60900213421 1550,2100 r90 top
SH-J2 "60900213421" Wurth_60900213421 1110,2105 r90 top
SH-J3 "60900213421" Wurth_60900213421 1755,2095 r90 top
SH-J4 "60900213421" Wurth_60900213421 1000,2105 r90 top
SH-J5 "60900213421" Wurth_60900213421 745,2105 r90 top
SH-J6 "60900213421" Wurth_60900213421 650,2095 r90 top
SH-J7 "60900213421" Wurth_60900213421 545,2095 r90 top
SH-J8 "60900213421" Wurth_60900213421 450,2100 r90 top
SH-J9 "60900213421" Wurth_60900213421 1050,1895 r180 top
SH-J11 "60900213421" Wurth_60900213421 1650,2100 r90 top
U1 "MSP430FR6047IPZR" PZ0100A_N 1650,3225 r0 top
U2 "TPS78001DDCR" DDC0005A_N 745,3674.69 r0 top
U3 "TPS62740DSSR" DSS0012A 655,3960 r180 top
U100 "MSP430F5528IRGCR" RGC0064B 541.39,1121.5 r0 top
U101 "TS5A21366RSER" RSE0008A 255,386.5 r270 top
U102 "MSP430G2452IRSA16T" RSA0016B 555,636.5 r90 top
U103 "TPD4E002DRL2" DRL0005A 1015,1495 r270 top
U200 "MSP430F5528IRGCR" RGC0064B 1385,1275 r180 top
U201 "TPD4E002DRL2" DRL0005A 1375,1805 r180 top
U202 "TPD4E002DRL2" DRL0005A 1650,1790 r180 top
U400 "TPD2E001DRLR" DRL0005A 1460,380 r180 top
U401 "TUSB2046BIRHBR" RHB0032E 1110,530 r180 top
U402 "TPS73533DRBR" DRB0008A 1595,720 r0 top
USB "1051640001" Molex_1051640001 1440,0 r0 top
Y1 "ABM3-8.000MHZ-D2Y-T" Abracon_ABM3 1140,3205 r0 top
Y2 "ABS07-32.768KHZ-9-T" XTAL_ABS07 985,3430 r180 top
Y3 "AWSCR-8.00CV-T" Abracon_AWSCR-CV 1315.35,3740.12 r0 top
ZZ2 "These assemblies are ESD sensitive, ESD precautions shall be observed." AssemblyNote 6625,-800.89 r0 top
ZZ3 "These assemblies must be clean and free from flux and all contaminants. Use of no clean flux is not acceptable." AssemblyNote 6625,-889.44 r0 top
ZZ4 "These assemblies must comply with workmanship standards IPC-A-610 Class 2, unless otherwise specified." AssemblyNote 6625,-978 r0 top

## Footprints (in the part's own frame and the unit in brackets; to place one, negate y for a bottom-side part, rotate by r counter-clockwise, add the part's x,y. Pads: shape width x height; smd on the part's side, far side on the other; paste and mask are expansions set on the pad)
0402 [mm] "0402 from SM-752 data"
  rect 0.8x0.6 smd: 1(-0.6,0) 2(0.6,0)
  body extent -0.55,-0.3 0.55,0.3, height 0.6
0402S [mil] "Based on C0402S footprint from PADS legacy"
  rect 15x24 smd: 1(-20,0) 2(20,0)
  body extent -22,-12 22,12, height 24
0603S [mil]
  rect 20x35 smd: 1(-30,0) 2(30,0)
  silkscreen extent -10,-17 10,17, body extent -34,-19 34,19, height 39
0805 [mm] "0805 from SM-752 data"
  rect 1.3x1.5 smd: 1(-0.85,0) 2(0.85,0)
  silkscreen extent -1.72,-0.97 1.72,0.97, body extent -1.1,-0.72 1.1,0.72, height 1.45
0805_HV [mil] "0805 with 30mil clearance between pads"
  rect 50x63 smd: 1(-40,0) 2(40,0)
  silkscreen extent -74,-40 74,40, body extent -43,-29 43,29, height 57
0805L [mm] "0805 from SM-752 data"
  rect 1.1x1.4 smd: 1(-0.75,0) 2(0.75,0)
  body extent -1.1,-0.72 1.1,0.72, height 1.45
Abracon_ABM3 [mm] "Abracon recommended land pattern 12.28.10"
  rect 1.9x2.4 smd: 1(-2.05,0) 2(2.05,0)
  body extent -2.6,-1.7 2.6,1.7, height 1.3
Abracon_AWSCR-CV [mm] "SMD, 3-Leads, Body 3.7x3.1mm, Pitch 1.5mm"
  rrect14% 0.7x4.1 smd: 1(-1.5,0) 3(1.5,0)
  rrect10% 1x4.1 smd: 2(0,0)
  silkscreen extent -2.2,-2.4 2.2,2.4, body extent -1.85,-1.55 1.85,1.56, height 1.21
ADKOM_FH-1138P [mm] "TH, 38-Leads, Body 56x25.1mm"
  rrect50% 1.5x1.5 hole 0.9: 1(-12.7,24.13)
  round 1.5 hole 0.9: 2(-12.7,21.59) 3(-12.7,19.05) 4(-12.7,16.51) 5(-12.7,13.97) 6(-12.7,11.43) 7(-12.7,8.89) 8(-12.7,6.35) 9(-12.7,3.81) 10(-12.7,1.27) 11(-12.7,-1.27) 12(-12.7,-3.81) 13(-12.7,-6.35) 14(-12.7,-8.89) 15(-12.7,-11.43) 16(-12.7,-13.97) 17(-12.7,-16.51) 18(-12.7,-19.05) 19(-12.7,-21.59) 20(-12.7,-24.13) 21(12.7,-21.59) 22(12.7,-19.05) 23(12.7,-16.51) 24(12.7,-13.97) 25(12.7,-11.43) 26(12.7,-8.89) 27(12.7,-6.35) 28(12.7,-3.81) 29(12.7,-1.27) 30(12.7,1.27) 31(12.7,3.81) 32(12.7,6.35) 33(12.7,8.89) 34(12.7,11.43) 35(12.7,13.97) 36(12.7,16.51) 37(12.7,19.05) 38(12.7,21.59)
  silkscreen extent -12.55,-28.38 12.55,28, body extent -12.85,-28.38 12.85,27.5, height 3.1
AssemblyNote [mil] "Assembly Note"
Bumpon_SJ61A1 [mil] "3M Cylindrical Bumpon black"
  round 1 on Mech4: 0(0,0)
  silkscreen extent -156,-156 156,156, body extent -156,-156 156,156, height 201
CE_Mark_5mm [mil] "Minimum text height for CE Mark"
  silkscreen extent -138,-98 138,98
CONN_PEC04DAAN [mm] "SULLINS"
  rect 1.65x1.65 hole 1.016 mask+0: 1(-3.81,-1.27)
  round 1.65 hole 1.016 mask+0: 2(-3.81,1.27) 3(-1.27,-1.27) 4(-1.27,1.27) 5(1.27,-1.27) 6(1.27,1.27) 7(3.81,-1.27) 8(3.81,1.27)
  silkscreen extent -6.18,-2.6 5.08,2.54, body extent -5.08,-2.54 5.08,2.54, height 8.38
CONN_SBH11-PBPC-D07-ST-BK [mm] "Sullins recommended land pattern"
  rect 1.65x1.65 hole 1.016 mask+0: 1(-7.62,-1.27)
  round 1.65 hole 1.016 mask+0: 2(-7.62,1.27) 3(-5.08,-1.27) 4(-5.08,1.27) 5(-2.54,-1.27) 6(-2.54,1.27) 7(0,-1.27) 8(0,1.27) 9(2.54,-1.27) 10(2.54,1.27) 11(5.08,-1.27) 12(5.08,1.27) 13(7.62,-1.27) 14(7.62,1.27)
  silkscreen extent -12.64,-5.08 12.64,4.7, body extent -12.64,-4.4 12.64,4.7, height 9.12
DDC0005A_N [mm]
  rrect17% 1x0.6 smd: 1(-1.375,0.95) 2(-1.375,0) 3(-1.375,-0.95) 4(1.375,-0.95) 5(1.375,0.95)
  silkscreen extent -1.75,-1.52 0.88,1.53, body extent -1.41,-1.45 1.41,1.45, height 1.1
DRB0008A [mm] "SON, 8-Leads, Body 3x3mm, Pitch 0.65mm, Thermal Pad 1.75x1.5mm, TI Recommended"
  oval 0.6x0.3 smd: 1(-1.4,0.975) 2(-1.4,0.325) 3(-1.4,-0.325) 4(-1.4,-0.975) 5(1.4,-0.975) 6(1.4,-0.325) 7(1.4,0.325) 8(1.4,0.975)
  rect 1.5x1.75 smd paste-0.75: 9(0,0)
  Top Layer region: -0.465,-1.5 -0.465,-0.875 -0.75,-0.875 -0.75,0.875 -0.465,0.875 -0.465,1.5 -0.185,1.5 -0.185,0.875 0.185,0.875 0.185,1.5 0.465,1.5 0.465,0.875 0.75,0.875 0.75,-0.875 0.465,-0.875 0.465,-1.5 0.185,-1.5 0.185,-0.875 -0.185,-0.875 -0.185,-1.5
  silkscreen extent -1.73,-1.73 1.73,1.73, body extent -1.57,-1.57 1.58,1.58, height 1.01
DRL0005A [mm] "SOTFL, 5-Flat Leads, Body 1.2x1.6x0.6mm, Pitch 0.5mm, TI recommended"
  rect 0.5x0.3 smd: 1(-0.75,0.5) 2(-0.75,0) 3(-0.75,-0.5) 4(0.75,-0.5) 5(0.75,0.5)
  silkscreen extent -0.9,-0.95 0.9,0.95, body extent -0.85,-0.85 0.85,0.85, height 0.62
DSS0012A [mm] "SON, 12-Leads, Body 2x3mm, Pitch 0.5mm, Thermal Pad 2x0.9mm, TI Recommended"
  rrect40% 0.5x0.25 smd: 1(-0.95,1.25) 2(-0.95,0.75) 3(-0.95,0.25) 4(-0.95,-0.25) 5(-0.95,-0.75) 6(-0.95,-1.25) 7(0.95,-1.25) 8(0.95,-0.75) 9(0.95,-0.25) 10(0.95,0.25) 11(0.95,0.75) 12(0.95,1.25)
  rrect11% 0.9x0.9 on Top Paste: 13(0,0.55) 13(0,-0.55)
  rrect11% 0.9x2 smd paste-0.45: 13(0,0)
  silkscreen extent -1.05,-1.7 1.05,1.7, body extent -1,-1.5 1,1.5, height 0.8
EURoHS_Exempt_60mil [mil] "EU RoHS Exempt symbol"
FCC_disclaimer [mil]
Fiducial10-30 [mm]
  round 1 smd mask+1: 1(0,0)
  Top Layer keep-out circle w1.678: c0,0 r0.75
LED_LTST-C190_Red [mm] "Lite-On"
  rect 0.8x0.8 smd: 1(-0.75,0) 2(0.75,0)
  silkscreen extent -1.1,-0.8 1.8,0.8, body extent -0.85,-0.45 0.85,0.45, height 0.9
LTST-C191_Green [mm] "Lite-On"
  rect 0.8x0.8 smd: 1(-0.75,0) 2(0.75,0)
  silkscreen extent -1.1,-0.8 1.8,0.8, body extent -0.85,-0.45 0.85,0.45, height 0.65
Molex_1051640001 [mm] "Receptacle, USB 2.0, Micro B, 5 Pos, 0.65mm Pitch, R/A, SMT"
  rrect22% 0.45x1.38 smd: 1(1.3,4.11) 2(0.65,4.11) 3(0,4.11) 4(-0.65,4.11) 5(-1.3,4.11)
  rrect7% 1.475x2.1 smd: 6(-2.462,3.75) 11(2.462,3.75)
  rrect100% 1.4x2.1 hole 0.6 slot 1.3 at 90 deg: 7(-3.95,1.45) 10(3.95,1.45)
  rrect7% 1.375x1.9 smd: 8(-0.937,1.45) 9(0.937,1.45)
  silkscreen extent 1.2,5.1 1.4,5.4, body extent -4.1,-0.7 4.1,4.47, height 2.45
Murata_CSTCR [mm] "Murata"
  rect 0.4x2.6 smd mask+0.051: 1(-1.5,0) 2(0,0) 3(1.5,0)
  Top Layer region: -0.4,0.8 0.4,0.8 0.4,1.3 -0.4,1.3
  Top Layer region: -0.4,-1.35 -0.4,-0.85 0.4,-0.85 0.4,-1.35
  Top Layer region: -0.4,-1.35 -0.4,-0.85 0.4,-0.85 0.4,-1.35
  Top Layer region: -1.9,0.8 -1.1,0.8 -1.1,1.3 -1.9,1.3
  Top Layer region: -1.9,-1.35 -1.9,-0.85 -1.1,-0.85 -1.1,-1.35
  Top Layer region: -1.9,-1.35 -1.9,-0.85 -1.1,-0.85 -1.1,-1.35
  Top Layer region: 1.1,0.8 1.9,0.8 1.9,1.3 1.1,1.3
  Top Layer region: 1.1,-1.35 1.1,-0.85 1.9,-0.85 1.9,-1.35
  Top Layer region: 1.1,-1.35 1.1,-0.85 1.9,-0.85 1.9,-1.35
  silkscreen extent -2.61,-1.56 2.32,1.08, body extent -2.3,-1.05 2.3,1.05, height 1.2
Net-Tie_50milWide_30milLong [mil] "50mil net tie, no solder mask opening, no solder paste"
  rect 30x50 smd paste-20 mask-20: 1(-15,0) 2(15,0)
PZ0100A_N [mm] "TSQFP, 100-Leads, Body 16.2x16.2mm (max), Pitch 0.50mm, IPC Medium Density"
  oval 1.45x0.3 smd: 1(-7.725,6) 2(-7.725,5.5) 3(-7.725,5) 4(-7.725,4.5) 5(-7.725,4) 6(-7.725,3.5) 7(-7.725,3) 8(-7.725,2.5) 9(-7.725,2) 10(-7.725,1.5) 11(-7.725,1) 12(-7.725,0.5) 13(-7.725,0) 14(-7.725,-0.5) 15(-7.725,-1) 16(-7.725,-1.5) 17(-7.725,-2) 18(-7.725,-2.5) 19(-7.725,-3) 20(-7.725,-3.5) 21(-7.725,-4) 22(-7.725,-4.5) 23(-7.725,-5) 24(-7.725,-5.5) 25(-7.725,-6) 51(7.725,-6) 52(7.725,-5.5) 53(7.725,-5) 54(7.725,-4.5) 55(7.725,-4) 56(7.725,-3.5) 57(7.725,-3) 58(7.725,-2.5) 59(7.725,-2) 60(7.725,-1.5) 61(7.725,-1) 62(7.725,-0.5) 63(7.725,0) 64(7.725,0.5) 65(7.725,1) 66(7.725,1.5) 67(7.725,2) 68(7.725,2.5) 69(7.725,3) 70(7.725,3.5) 71(7.725,4) 72(7.725,4.5) 73(7.725,5) 74(7.725,5.5) 75(7.725,6)
  oval 0.3x1.45 smd: 26(-6,-7.725) 27(-5.5,-7.725) 28(-5,-7.725) 29(-4.5,-7.725) 30(-4,-7.725) 31(-3.5,-7.725) 32(-3,-7.725) 33(-2.5,-7.725) 34(-2,-7.725) 35(-1.5,-7.725) 36(-1,-7.725) 37(-0.5,-7.725) 38(0,-7.725) 39(0.5,-7.725) 40(1,-7.725) 41(1.5,-7.725) 42(2,-7.725) 43(2.5,-7.725) 44(3,-7.725) 45(3.5,-7.725) 46(4,-7.725) 47(4.5,-7.725) 48(5,-7.725) 49(5.5,-7.725) 50(6,-7.725) 76(6,7.725) 77(5.5,7.725) 78(5,7.725) 79(4.5,7.725) 80(4,7.725) 81(3.5,7.725) 82(3,7.725) 83(2.5,7.725) 84(2,7.725) 85(1.5,7.725) 86(1,7.725) 87(0.5,7.725) 88(0,7.725) 89(-0.5,7.725) 90(-1,7.725) 91(-1.5,7.725) 92(-2,7.725) 93(-2.5,7.725) 94(-3,7.725) 95(-3.5,7.725) 96(-4,7.725) 97(-4.5,7.725) 98(-5,7.725) 99(-5.5,7.725) 100(-6,7.725)
  silkscreen extent -7.7,-6.3 6.3,6.82, body extent -8.01,-8.01 8.01,8.01, height 1.6
RGC0064B [mm]
  oval 0.6x0.24 smd mask+0.07: 1(-4.4,3.75) 2(-4.4,3.25) 3(-4.4,2.75) 4(-4.4,2.25) 5(-4.4,1.75) 6(-4.4,1.25) 7(-4.4,0.75) 8(-4.4,0.25) 9(-4.4,-0.25) 10(-4.4,-0.75) 11(-4.4,-1.25) 12(-4.4,-1.75) 13(-4.4,-2.25) 14(-4.4,-2.75) 15(-4.4,-3.25) 16(-4.4,-3.75) 33(4.4,-3.75) 34(4.4,-3.25) 35(4.4,-2.75) 36(4.4,-2.25) 37(4.4,-1.75) 38(4.4,-1.25) 39(4.4,-0.75) 40(4.4,-0.25) 41(4.4,0.25) 42(4.4,0.75) 43(4.4,1.25) 44(4.4,1.75) 45(4.4,2.25) 46(4.4,2.75) 47(4.4,3.25) 48(4.4,3.75)
  oval 0.24x0.6 smd mask+0.07: 17(-3.751,-4.4) 18(-3.251,-4.4) 19(-2.751,-4.4) 20(-2.251,-4.4) 21(-1.75,-4.4) 22(-1.25,-4.4) 23(-0.75,-4.4) 24(-0.25,-4.4) 25(0.25,-4.4) 26(0.75,-4.4) 27(1.25,-4.4) 28(1.75,-4.4) 29(2.251,-4.4) 30(2.751,-4.4) 31(3.251,-4.4) 32(3.751,-4.4) 49(3.751,4.4) 50(3.251,4.4) 51(2.751,4.4) 52(2.251,4.4) 53(1.75,4.4) 54(1.25,4.4) 55(0.75,4.4) 56(0.25,4.4) 57(-0.25,4.4) 58(-0.75,4.4) 59(-1.25,4.4) 60(-1.75,4.4) 61(-2.251,4.4) 62(-2.751,4.4) 63(-3.251,4.4) 64(-3.751,4.4)
  rect 4.25x4.25 smd paste-2.112: 65(0,0)
  silkscreen extent -5.1,-5.1 5.1,5.1, body extent -4.57,-4.57 4.57,4.57, height 1.01
RHB0032E [mm] "QFN, 32-Leads, Body 5x5mm, Pitch 0.5mm, Thermal Pad 3.45x3.45mm, TI Recommended"
  oval 0.6x0.24 smd: 1(-2.4,1.75) 2(-2.4,1.25) 3(-2.4,0.75) 4(-2.4,0.25) 5(-2.4,-0.25) 6(-2.4,-0.75) 7(-2.4,-1.25) 8(-2.4,-1.75) 17(2.4,-1.75) 18(2.4,-1.25) 19(2.4,-0.75) 20(2.4,-0.25) 21(2.4,0.25) 22(2.4,0.75) 23(2.4,1.25) 24(2.4,1.75)
  oval 0.24x0.6 smd: 9(-1.75,-2.4) 10(-1.25,-2.4) 11(-0.75,-2.4) 12(-0.25,-2.4) 13(0.25,-2.4) 14(0.75,-2.4) 15(1.25,-2.4) 16(1.75,-2.4) 25(1.75,2.4) 26(1.25,2.4) 27(0.75,2.4) 28(0.25,2.4) 29(-0.25,2.4) 30(-0.75,2.4) 31(-1.25,2.4) 32(-1.75,2.4)
  rect 3.45x3.45 smd paste-1.725: 33(0,0)
  silkscreen extent -2.72,-2.73 2.72,2.73, body extent -2.57,-2.57 2.58,2.58, height 1.01
RSA0016B [mm] "QFN, 16-Leads, Body 4x4mm, Pitch 0.65mm, Thermal Pad 2.7x2.7mm, TI Recommended"
  oval 0.6x0.3 smd: 1(-1.9,0.975) 2(-1.9,0.325) 3(-1.9,-0.325) 4(-1.9,-0.975) 9(1.9,-0.975) 10(1.9,-0.325) 11(1.9,0.325) 12(1.9,0.975)
  oval 0.3x0.6 smd: 5(-0.975,-1.9) 6(-0.325,-1.9) 7(0.325,-1.9) 8(0.975,-1.9) 13(0.975,1.9) 14(0.325,1.9) 15(-0.325,1.9) 16(-0.975,1.9)
  rect 2.7x2.7 smd paste-1.35: 17(0,0)
  Top Layer keep-out region: -2,1.5 -1.5,1.5 -1.5,2 -2,2
  silkscreen extent -2.2,-2.2 2.2,2.2, body extent -2.05,-2.05 2.05,2.05, height 1.01
RSE0008A [mm] "QFN, 8-Leads, Body 1.5x1.5mm, Pitch 0.5mm, TI Recommended"
  rect 0.55x0.25 smd: 1(-0.65,0.5) 3(-0.65,-0.5) 5(0.65,-0.5) 7(0.65,0.5)
  rect 0.55x0.2 smd: 2(-0.65,0) 6(0.65,0)
  rect 0.3x0.6 smd: 4(0,-0.65) 8(0,0.65)
  silkscreen extent -1.02,-0.92 0.77,0.92, body extent -0.77,-0.77 0.77,0.77, height 0.61
SAMTEC_HMTSW-102-07-G-S-240 [mm] "Header, 2.54mm, 2x1, TH"
  rect 1.55x1.55 hole 1.02: 1(-1.27,0)
  round 1.55 hole 1.02: 2(1.27,0)
  silkscreen extent -3.01,-1.24 2.54,1.27, body extent -2.54,-1.27 2.54,1.27, height 8.64
SOT-23 [mm] "SOT23, 3-Leads, Body 2.9x1.3mm, Pitch 0.95mm, Lead Span 2.5mm, IPC Medium Density"
  rrect50% 1x0.6 smd: 1(-1.2,0.95) 2(-1.2,-0.95) 3(1.2,0)
  silkscreen extent -1.63,-1.5 0.7,1.5, body extent -1.16,-1.45 1.21,1.45, height 1
SOT-323 [mm] "Zetex recommended land pattern.  March 2007"
  rect 0.8x0.6 smd: 1(-0.8,0.65) 2(-0.8,-0.65) 3(0.8,0)
  silkscreen extent -1.14,-1.22 0.77,1.22, body extent -1.13,-1.13 1.12,1.12, height 1.13
Sullins_PxC02DAAN [mm] "Header, 2.54mm, 2x2, TH"
  rect 1.7x1.7 hole 1.2: 1(-1.27,1.27)
  round 1.7 hole 1.2: 2(1.27,1.27) 3(-1.27,-1.27) 4(1.27,-1.27)
  silkscreen extent -2.61,-2.8 2.61,3.2, body extent -2.61,-2.8 2.61,2.8, height 8.58
Sullins_xxC07SAAN [mm] "Header, 2.54 mm, 7x1, TH"
  rect 1.55x1.55 hole 1.016: 1(-7.62,0)
  round 1.55 hole 1.016: 2(-5.08,0) 3(-2.54,0) 4(0,0) 5(2.54,0) 6(5.08,0) 7(7.62,0)
  silkscreen extent -8.89,-1.27 8.89,1.7, body extent -8.89,-1.27 8.89,1.27, height 8.38
SW_B3U-1000P [mm] "OMRON"
  rect 0.8x1.7 smd: 1(-1.7,0) 2(1.7,0)
  silkscreen extent -1.5,-1.25 1.5,1.25, body extent -1.5,-1.25 1.5,1.25, height 1.75
SW_SS-13D16-VG [mm] "TH, 4-Leads, Body 12.6x4.3mm, Pitch 2mm"
  rect 1.3x1.3 hole 0.8: 1(-4,0)
  round 1.3 hole 0.8: 2(0,0) 3(2,0) 4(4,0)
  round 1.75 hole 1.25: S1(-6.1,0) S2(6.1,0)
  silkscreen extent -6.3,-2.75 6.3,2.15, body extent -6.3,-2.15 6.3,2.15, height 8.7
SW_TL1015AF160QG [mm] "E-Switch"
  rect 0.95x1.4 smd: 1(-2.1,0) 2(2.1,0)
  silkscreen extent -2,-1.5 2,1.5, body extent -2.3,-1.5 2.3,1.5, height 2
TI_Stacked_Overlay_Small [mil]
  silkscreen extent -418,-98 418,98
TRIM_3224W [mm] "BOURNS"
  rect 1.6x1.3 smd: 1(-1.45,1.25) 3(-1.45,-1.25)
  rect 1.6x2 smd: 2(1.45,0)
  silkscreen extent -1.9,-2.6 1.9,2.6, body extent -1.8,-2.5 1.8,2.5, height 5.31
TSW-102-07-G-D [mm] "Samtec 100mil, 2x2, 230 mil above insulator"
  rrect6% 1.65x1.65 hole 1.016: 1(-1.27,-1.27)
  round 1.65 hole 1.016: 2(-1.27,1.27) 3(1.27,-1.27) 4(1.27,1.27)
  silkscreen extent -3.57,-2.54 2.54,2.54, body extent -2.54,-2.54 2.54,2.54, height 8.38
TSW-102-07-G-S [mm] "Samtec 100mil, 1x2, 230 mil above insulator"
  rrect6% 1.65x1.65 hole 1.016: 1(-1.27,0)
  round 1.65 hole 1.016: 2(1.27,0)
  silkscreen extent -2.54,-1.27 2.54,1.65, body extent -2.54,-1.27 2.54,1.27, height 8.38
TSW-104-07-G-D [mm] "Samtec 100mil, 2x4, 230 mil above insulator"
  rrect6% 1.65x1.65 hole 1.016: 1(-3.81,-1.27)
  round 1.65 hole 1.016: 2(-3.81,1.27) 3(-1.27,-1.27) 4(-1.27,1.27) 5(1.27,-1.27) 6(1.27,1.27) 7(3.81,-1.27) 8(3.81,1.27)
  silkscreen extent -6.1,-2.54 5.08,2.54, body extent -5.08,-2.54 5.08,2.54, height 8.38
TSW-110-07-G-D [mm] "Samtec 100mil, 2x10, 230 mil above insulator"
  rrect6% 1.65x1.65 hole 1.016: 1(-11.43,-1.27)
  round 1.65 hole 1.016: 2(-11.43,1.27) 3(-8.89,-1.27) 4(-8.89,1.27) 5(-6.35,-1.27) 6(-6.35,1.27) 7(-3.81,-1.27) 8(-3.81,1.27) 9(-1.27,-1.27) 10(-1.27,1.27) 11(1.27,-1.27) 12(1.27,1.27) 13(3.81,-1.27) 14(3.81,1.27) 15(6.35,-1.27) 16(6.35,1.27) 17(8.89,-1.27) 18(8.89,1.27) 19(11.43,-1.27) 20(11.43,1.27)
  silkscreen extent -13.72,-2.54 12.7,2.54, body extent -12.7,-2.54 12.7,2.54, height 8.38
VLF302515MT [mm] "TDK"
  rect 0.9x1.45 smd: 1(-0.85,0) 2(0.85,0)
  silkscreen extent -1.45,-1.68 1.45,1.68, body extent -1.35,-1.6 1.35,1.6, height 1.5
WEEE_Minimum [mil] "WEEElie bin"
  silkscreen extent -95,-172 99,104
Wurth_60900213421 [mil] "Shunt, 2.54mm, Black"
  round 1 on Mech3: 0(0,0)
  body extent -98,-48 98,48, height 236
WURTH_61300311121 [mm] "Header, 2.54mm, 3x1, TH"
  rect 1.65x1.65 hole 1.15: 1(-2.54,0)
  round 1.65 hole 1.15: 2(0,0) 3(2.54,0)
  silkscreen extent -3.81,-1.27 3.81,1.6, body extent -3.81,-1.27 3.81,1.27, height 8.54
WURTH_61301021121 [mm] "Header, 2.54mm, 5x2, TH"
  rect 1.65x1.65 hole 1.15: 1(-5.08,-1.27)
  round 1.65 hole 1.15: 2(-5.08,1.27) 3(-2.54,-1.27) 4(-2.54,1.27) 5(0,-1.27) 6(0,1.27) 7(2.54,-1.27) 8(2.54,1.27) 9(5.08,-1.27) 10(5.08,1.27)
  silkscreen extent -6.35,-2.54 6.35,2.9, body extent -6.35,-2.54 6.35,2.54, height 8.54
XTAL_ABS07 [mm] "ABRACON"
  rect 1.1x1.9 smd: 1(-1.25,0) 2(1.25,0)
  silkscreen extent -0.4,-1 0.4,1, body extent -1.65,-0.8 1.65,0.8, height 0.9

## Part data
BUT_DOWN BUT_LEFT BUT_RIGHT BUT_SELECT BUT_UP: "Switch, Tactile, SPST-NO, 0.05A, 12V, SMT", CurrentRating_mA=50, Manufacturer=E-Switch, Supplier Part Number 1=EG4344CT-ND
C1 C2 C5 C6 C13 C20 C28 C102 C104 C108 C113 C118 C119 C121 C202 C203 C204 C400 C402 C408 C409 C411: "CAP, CERM, 0.1 µF, 16 V, +/- 10%, X7R, 0402", Cap_Case=0402, Manufacturer=MuRata, Supplier Part Number 1=490-3261-1-ND, TempCo=X7R, Tolerance_%=10, Value1=Unknown, Value2=16V, ValueDisplayed=0.1µF
C3 C4 C14 C111 C210: "CAP, CERM, 1000 pF, 50 V, +/- 5%, C0G/NP0, 0402", Cap_Case=0402, Manufacturer=MuRata, Supplier Part Number 1=490-3244-1-ND, TempCo=C0G/NP0, Tolerance_%=5, Value1=Unknown, Value2=50V, ValueDisplayed=1000pF
C7 C8 C15 C16 C17 C18: "CAP, CERM, 12 pF, 50 V, +/- 5%, C0G/NP0, 0402", Cap_Case=0402, Manufacturer=MuRata, Supplier Part Number 1=81-GRM1555C1H120JA1D, TempCo=C0G/NP0, Tolerance_%=5, Value1=Unknown, Value2=50V, ValueDisplayed=12pF
C9: "CAP, CERM, 4.7 µF, 16 V, +/- 10%, X7R, 0805", Cap_Case=0805, Manufacturer=MuRata, Supplier Part Number 1=490-4522-1-ND, TempCo=X7R, Tolerance_%=10, Value1="0.006 ohm", Value2=16V, ValueDisplayed=4.7µF
C10 C19 C410 C413: "CAP, CERM, 10 µF, 10 V, +/- 20%, X5R, 0603", Cap_Case=0603, Manufacturer=MuRata, TempCo=X5R, Tolerance_%=20, Value1=Unknown, Value2=10V, ValueDisplayed=10µF
C11 C12: "CAP, CERM, 1000 pF, 50 V, +/- 1%, C0G/NP0, 0603", Cap_Case=0603, Manufacturer=MuRata, Supplier Part Number 1=490-6377-1-ND, TempCo=C0G/NP0, Tolerance_%=1%, Value1=Unknown, Value2=50V, ValueDisplayed=1000pF
C21 C23 C24: "CAP, CERM, 47 µF, 6.3 V, +/- 20%, X5R, 0805", Cap_Case=0805, Manufacturer=MuRata, Supplier Part Number 1=490-9960-1-ND, TempCo=X5R, Tolerance_%=20, Value1=Unknown, Value2=6.3V, ValueDisplayed=47µF
C22 C25 C26 C27: "CAP, CERM, 1 µF, 10 V, +/- 10%, X7R, 0603", Cap_Case=0603, Manufacturer=MuRata, Supplier Part Number 1=490-3899-1-ND, TempCo=X7R, Tolerance_%=10, Value1="0.011 ohm", Value2=10V, ValueDisplayed=1µF
C100 C101 C200 C201 C403 C404: "CAP, CERM, 22 pF, 50 V, +/- 5%, C0G/NP0, 0402", Cap_Case=0402, Manufacturer=MuRata, Supplier Part Number 1=81-GRM1555C1H220JA1D, TempCo=C0G/NP0, Tolerance_%=5, Value1=Unknown, Value2=50V, ValueDisplayed=22pF
C103 C112 C116 C117 C120 C205: "CAP, CERM, 4.7 µF, 10 V, +/- 20%, X5R, 0603", Cap_Case=0603, Manufacturer=MuRata, TempCo=X5R, Tolerance_%=20, Value1=Unknown, Value2=10V, ValueDisplayed=4.7µF
C105 C106 C206 C207: "CAP, CERM, 0.22 µF, 16 V, +/- 10%, X7R, 0402", Cap_Case=0402, Manufacturer=MuRata, Supplier Part Number 1=490-5418-1-ND, TempCo=X7R, Tolerance_%=10, Value1=Unknown, Value2=16V, ValueDisplayed=0.22µF
C107 C208: "CAP, CERM, 0.47 µF, 16 V, +/- 10%, X5R, 0402", Cap_Case=0402, Manufacturer=MuRata, TempCo=X5R, Tolerance_%=10, Value1=Unknown, Value2=16V, ValueDisplayed=0.47µF
C109 C110 C114 C115: "CAP, CERM, 33 pF, 50 V, +/-5%, C0G/NP0, 0402", Cap_Case=0402, Manufacturer=MuRata, Supplier Part Number 1=81-GRM1555C1H330JA1D, TempCo=C0G/NP0, Tolerance_%=5, Value1=Unknown, Value2=50V, ValueDisplayed=33pF
C401 C405 C406 C407: "CAP, CERM, 10 pF, 50 V, +/- 5%, C0G/NP0, 0402", Cap_Case=0402, Manufacturer=MuRata, Supplier Part Number 1=81-GRM1555C1H100JA1D, TempCo=C0G/NP0, Tolerance_%=5, Value1=Unknown, Value2=50V, ValueDisplayed=10pF
C412: "CAP, CERM, 0.01 µF, 16 V, +/- 10%, X7R, 0402", Cap_Case=0402, Manufacturer=MuRata, Supplier Part Number 1=490-1313-1-ND, TempCo=X7R, Tolerance_%=10, Value1=Unknown, Value2=16V, ValueDisplayed=0.01µF
D100 D203 LED3: "LED, Red, SMD", Color=red, Manufacturer=Lite-On, Power_TotalModule=0.0625, Supplier Part Number 1=160-1181-1-ND, Value1=0.0625W, Value2=2V
D101 D201 D202 LED1 LED2: "LED, Green, SMD", Color=green, Manufacturer=Lite-On, Supplier Part Number 1=160-1888-1-ND, Value1=W, Value2=3.2V
D102 D103: "Diode, Schottky, 40V, 0.2A, SOT-23", Manufacturer="Diodes Inc.", Supplier Part Number 1=BAS40-05DICT-ND, Value1=0.2A, Value2=0.9V
FID1 FID2 FID3: library part CMP-0077181-1, "Fiducial mark.  There is nothing to buy or mount.", Manufacturer=N/A
H1 H2 H3 H4: "Bumpon, Cylindrical, 0.312 X 0.200, Black", Manufacturer=3M, Supplier Part Number 1=SJ5746-0-ND
J1: "Header, 2.54 mm, 5x2, Gold, TH", Manufacturer="Wurth Elektronik", Supplier Part Number 1=732-2672-ND
J2: "Header, 2.54mm, 2x2, Gold, TH", Color=Black, Current_A=3, Manufacturer="Sullins Connector Solutions", Supplier Part Number 1=S2011E-02-ND, Voltage_V=1800
J3: "Header, 100mil, 4x2, Tin, TH", Color=Black, Current_A=3, Manufacturer="Sullins Connector Solutions", Supplier Part Number 1=S2012E-04-ND, Voltage_V=1800
J4 J7: "Header, 100mil, 2x1, Gold, TH", Manufacturer=Samtec, Supplier Part Number 1=HMTSW-102-07-G-S-240-ND
J5 J6: "Header, 100mil, 10x2, Gold, TH", Color=Black, Current_A=6.3, Manufacturer=Samtec, Supplier Part Number 1=SAM1028-10-ND, Voltage_V=550
J8: "Header, 100mil, 4x2, Gold, TH", Color=Black, Current_A=6.3, Manufacturer=Samtec, Supplier Part Number 1=SAM1028-04-ND, Voltage_V=550
J10: "Header, 2.54 mm, 3x1, Gold, TH", Manufacturer="Wurth Elektronik", Supplier Part Number 1=732-5316-ND
J30: "Header, 100mil, 2x2, Gold, TH", Color=Black, Current_A=6.3, Manufacturer=Samtec, Supplier Part Number 1=SAM1028-02-ND, Voltage_V=550
J31 J32 J33: "Header, 100mil, 2x1, Gold, TH", Color=Black, Current_A=6.3, Manufacturer=Samtec, Supplier Part Number 1=SAM1029-02-ND, Voltage_V=550
J34: "Header (shrouded), 100 mil, 7x2, Gold, TH", Manufacturer="Sullins Connector Solutions", Supplier Part Number 1=S9170-ND
J100 J200: "Header, 2.54 mm, 7x1, Gold, TH", Color=Black, Current_A=3, Manufacturer="Sullins Connector Solutions", Supplier Part Number 1=S1011E-07-ND, Voltage_V=1800
L1 L2: "Ferrite Bead, 600 ohm @ 100 MHz, 2 A, 0805", Manufacturer=TDK, Supplier Part Number 1=445-2206-1-ND, Value1="0.1 ohm", Value2=2A
L3: "Inductor, Shielded, Ferrite, 2.2 µH, 1.57 A, 0.042 ohm, SMD", Manufacturer=TDK, Supplier Part Number 1=445-9630-1-ND, Value1="0.042 ohm", Value2=1.57A, ValueDisplayed=2.2µH
L101: "Inductor, Shielded, Composite, 2.2uH, 0.95A, 0.16 ohm, SMD", Manufacturer=Samsung, Supplier Part Number 1=1276-6202-1-ND, Value1="0.16 ohm", Value2=0.95A, ValueDisplayed=2.2µH
LCD: "108 Segment LCD Display, TH", Manufacturer="Adkom Elektronik"
Logo1: library part TI_Logo, "Texas Instrument Corporate Signature"
Logo2: library part CMP-0074769-1
Logo3: library part FCC_disclaimer, "FCC_disclaimer"
Logo5: library part CMP-0074848-1
MCU_RESET S201 S202: "SWITCH TACTILE SPST-NO 0.05A 12V", CurrentRating_mA=50, Manufacturer="Omron Electronic Components", Supplier Part Number 1=SW1020CT-ND
NT1 NT2 NT3: "Single point connection between nets."
POW_SEL: "Switch, Slide, SP3T, On-On-On, 3 Pos, 0.3A, 30 VDC, TH", CurrentRating_mA=300, Manufacturer="C&K Components", Supplier Part Number 1=CKN10371-ND
Q100 Q200: "Resonator, 4MHz, 39pF SMD", Frequency="4 MHz", Frequency Stability="±0.08 %", Manufacturer=MuRata
Q101: library part BSS84W-7-F, "MOSFET, P-CH, -50V, -0.13A, SOT-323", Alternate Manufacturer=None, Manufacturer="Diodes Inc.", Supplier Part Number 1=BSS84W-FDICT-ND, Value1="10 ohm", Value2="? nC"
Q102: library part "BC850CLT1G, ON Semiconductor", "Transistor, NPN, 45V, 0.1A, SOT-23", Manufacturer="ON Semiconductor", Supplier Part Number 1=BC850CLT1GOSCT-ND, Value1=0.1A, Value2=800
Q400: "Resonator, 6MHz, 15pF SMD", Frequency="6 MHz", Frequency Stability="±0.2 %", Manufacturer=MuRata, Supplier Part Number 1=490-1218-1-ND
R1 R2 R3 R4 R6 R7 R8 R39 R40 R211: "RES, 100, 5%, 0.063 W, 0402", Manufacturer=Vishay-Dale, Power_W=0.063, Supplier Part Number 1=541-100JCT-ND, TempCo="200 ppm/C", Tolerance_%=5, Value1=5%, Value2=0.063W, Value_Code=100R, ValueDisplayed=100
R9 R10: "RES, 100 k, 5%, 0.063 W, 0402", Manufacturer=Vishay-Dale, Power_W=0.063, Supplier Part Number 1=71-CRCW0402J-100K-E3, TempCo="200 ppm/C", Tolerance_%=5, Value1=5%, Value2=0.063W, Value_Code=100k
R11: "Trimmer, 200 K, 0.25 W, SMD", Manufacturer=Bourns, Supplier Part Number 1=3224W-1-204ECT-ND
R12 R13 R14: "RES, 330 k, 5%, 0.063 W, 0402", Manufacturer=Vishay-Dale, Power_W=0.063, Supplier Part Number 1=541-330KJCT-ND, TempCo="200 ppm/C", Tolerance_%=5, Value1=5%, Value2=0.063W, Value_Code=330k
